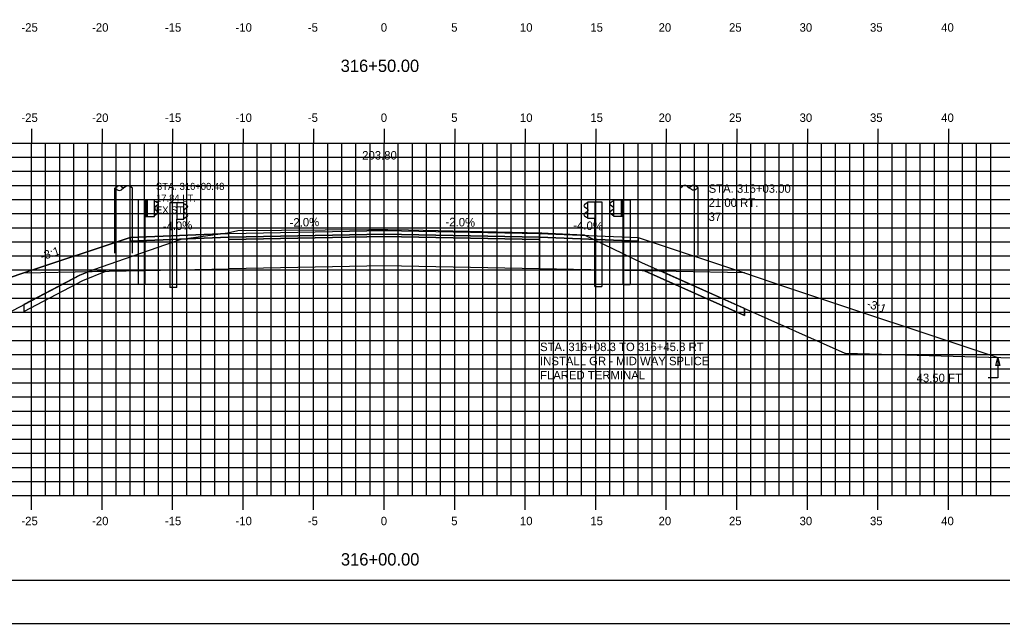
# Model space of a CAD drawing. Extents: x 1138763 to 1138933, y 608981 to 609091.
# Drawn here: x 1138820.4 to 1138890, y 608981.3 to 609024.1 of the extents above; entities that cross this region are included whole.
import ezdxf

# ---------------------------------------------------------------- set-up
doc = ezdxf.new("R2010")
doc.units = 0
for name, color, linetype in [('ANNOTATION', 7, 'Continuous'), ('BORDER', 7, 'Continuous'), ('D_Guardrail_Beam_Lt', 7, 'Continuous'), ('D_Guardrail_Beam_Rt', 7, 'Continuous'), ('D_Roadway_Centerline', 7, 'Continuous'), ('D_Roadway_Centerline_Text', 7, 'Continuous'), ('D_Roadway_Edge_Shoulder', 7, 'Continuous'), ('D_Roadway_Edge_TW', 7, 'Continuous'), ('D_Roadway_Pavement', 7, 'Continuous'), ('D_Roadway_SlopeLines', 7, 'Continuous'), ('D_Roadway_SubGrade', 7, 'Continuous'), ('D_Text_Monospaced', 7, 'Continuous'), ('D_Text_Standard', 7, 'Continuous'), ('D_Utilities_Pole_Joint_Rt', 7, 'Continuous'), ('H_V ANNOTATION', 7, 'Continuous'), ('MAJOR', 7, 'Continuous'), ('MINOR', 7, 'Continuous'), ('PLOT BOUNDARY', 7, 'Continuous'), ('S_Guardrail_Beam', 7, 'Continuous'), ('S_Roadway_Centerline', 7, 'Continuous'), ('S_Utilities_Pole_Power', 7, 'Continuous'), ('SHADING', 7, 'Continuous')]:
    doc.layers.add(name, color=color, linetype=linetype)

msp = doc.modelspace()

# ---------------------------------------------------------------- linework, layer by layer
msp.add_lwpolyline([(1138803.882, 609000.533), (1138817.659, 609005.125), (1138820.659, 609006.125), (1138828.191, 609008.636), (1138828.192, 609008.636), (1138835.192, 609008.916), (1138846.192, 609009.136), (1138857.192, 609008.916), (1138864.192, 609008.636), (1138871.724, 609006.125), (1138874.724, 609005.125), (1138889.689, 609000.137)])
at = {"layer": 'BORDER'}
msp.add_lwpolyline([(1138771.192, 608984.335), (1138931.192, 608984.335), (1138931.192, 609089.335), (1138771.192, 609089.335)], close=True, dxfattribs=at)
at = {"layer": 'D_Guardrail_Beam_Lt'}
for p, q in [((1138828.763, 609011.299), (1138828.763, 609005.299)), ((1138829.234, 609011.299), (1138828.763, 609011.299)), ((1138829.921, 609011.299), (1138829.234, 609011.299)), ((1138829.234, 609011.299), (1138829.234, 609010.132)), ((1138829.296, 609011.299), (1138829.296, 609010.132)), ((1138829.4, 609011.299), (1138829.4, 609010.132)), ((1138829.921, 609010.132), (1138829.921, 609011.299)), ((1138829.921, 609011.216), (1138829.995, 609011.201)), ((1138830.011, 609011.194), (1138830.155, 609011.094)), ((1138862.373, 609011.194), (1138862.23, 609011.094)), ((1138862.463, 609011.216), (1138862.389, 609011.201)), ((1138829.926, 609010.751), (1138829.926, 609010.681)), ((1138830.155, 609010.951), (1138829.959, 609010.815)), ((1138829.959, 609010.616), (1138830.155, 609010.48)), ((1138862.23, 609010.951), (1138862.425, 609010.815)), ((1138862.425, 609010.616), (1138862.23, 609010.48)), ((1138862.459, 609010.751), (1138862.459, 609010.681)), ((1138829.234, 609010.132), (1138829.921, 609010.132)), ((1138829.255, 609005.299), (1138829.255, 609010.132)), ((1138829.995, 609010.23), (1138829.921, 609010.216)), ((1138830.155, 609010.337), (1138830.011, 609010.237)), ((1138862.23, 609010.337), (1138862.373, 609010.237)), ((1138862.389, 609010.23), (1138862.463, 609010.216)), ((1138829.255, 609005.299), (1138828.763, 609005.299))]:
    msp.add_line(p, q, dxfattribs=at)
for centre, major_axis, start_param, end_param in [((1138829.987, 609011.16), (0.0417, 0), 0.959931, 1.376053), ((1138862.397, 609011.16), (-0.0417, 0), 4.907132, 5.323254), ((1138830.005, 609010.751), (-0.0789, 0), 5.323254, 6.283185), ((1138830.005, 609010.681), (-0.0789, 0), 6.283185, 7.243116), ((1138830.104, 609011.023), (0.0877, 0), 5.323254, 7.243116), ((1138830.104, 609010.409), (0.0877, 0), 5.323254, 7.243116), ((1138862.28, 609011.023), (-0.0877, 0), 5.323254, 7.243116), ((1138862.28, 609010.409), (-0.0877, 0), 5.323254, 7.243116), ((1138862.38, 609010.751), (0.0789, 0), 0, 0.959931), ((1138862.38, 609010.681), (0.0789, 0), 5.323254, 6.283185), ((1138829.987, 609010.271), (0.0417, 0), 4.907132, 5.323254), ((1138862.397, 609010.271), (-0.0417, 0), 0.959931, 1.376053)]:
    msp.add_ellipse(centre, major_axis=major_axis, ratio=0.995501, start_param=start_param, end_param=end_param, dxfattribs=at)
at = {"layer": 'D_Guardrail_Beam_Rt'}
for p, q in [((1138862.463, 609011.299), (1138863.15, 609011.299)), ((1138862.463, 609010.132), (1138862.463, 609011.299)), ((1138862.984, 609011.299), (1138862.984, 609010.132)), ((1138863.088, 609011.299), (1138863.088, 609010.132)), ((1138863.15, 609011.299), (1138863.621, 609011.299)), ((1138863.15, 609011.299), (1138863.15, 609010.132)), ((1138863.621, 609011.299), (1138863.621, 609005.299)), ((1138863.15, 609010.132), (1138862.463, 609010.132)), ((1138863.13, 609005.299), (1138863.13, 609010.132)), ((1138863.13, 609005.299), (1138863.621, 609005.299))]:
    msp.add_line(p, q, dxfattribs=at)
at = {"layer": 'D_Roadway_Edge_Shoulder'}
for points in [[(1138835.192, 609008.916), (1138828.192, 609008.636), (1138828.192, 609008.386), (1138835.192, 609008.666)], [(1138857.192, 609008.916), (1138864.192, 609008.636), (1138864.192, 609008.386), (1138857.192, 609008.666)]]:
    msp.add_lwpolyline(points, close=True, dxfattribs=at)
at = {"layer": 'D_Roadway_Edge_TW'}
msp.add_lwpolyline([(1138835.192, 609008.666), (1138835.192, 609008.916), (1138846.192, 609009.136), (1138857.192, 609008.916), (1138857.192, 609008.666), (1138846.192, 609008.886)], close=True, dxfattribs=at)
at = {"layer": 'D_Roadway_Pavement'}
msp.add_lwpolyline([(1138835.192, 609008.499), (1138835.192, 609008.666), (1138846.192, 609008.886), (1138857.192, 609008.666), (1138857.192, 609008.499), (1138846.192, 609008.719)], close=True, dxfattribs=at)
at = {"layer": 'D_Roadway_SlopeLines'}
for points in [[(1138820.659, 609006.125), (1138817.659, 609005.125)], [(1138820.659, 609003.884), (1138820.659, 609003.384), (1138824.82, 609005.58), (1138826.47, 609006.241)], [(1138871.724, 609003.612), (1138871.724, 609003.112), (1138864.658, 609006.266)], [(1138871.724, 609006.125), (1138874.724, 609005.125)], [(1138874.724, 609005.125), (1138889.689, 609000.137)]]:
    msp.add_lwpolyline(points, dxfattribs=at)
at = {"layer": 'D_Roadway_SubGrade'}
for points in [[(1138835.192, 609008.499), (1138835.192, 609008.666), (1138828.192, 609008.386), (1138828.192, 609008.636), (1138828.191, 609008.636), (1138820.659, 609006.125), (1138835.192, 609006.416)], [(1138835.192, 609006.416), (1138835.192, 609008.499), (1138846.192, 609008.719), (1138857.192, 609008.499), (1138857.192, 609006.416), (1138846.192, 609006.636)], [(1138857.192, 609008.499), (1138857.192, 609008.666), (1138864.192, 609008.386), (1138864.192, 609008.636), (1138864.192, 609008.636), (1138871.724, 609006.125), (1138857.192, 609006.416)]]:
    msp.add_lwpolyline(points, close=True, dxfattribs=at)
at = {"layer": 'D_Text_Standard'}
msp.add_lwpolyline([(1138889.689, 609000.137), (1138889.686, 608998.68), (1138889.006, 608998.68)], dxfattribs=at)
msp.add_lwpolyline([(1138889.689, 609000.137), (1138889.834, 608999.554), (1138889.543, 608999.555)], close=True, dxfattribs=at)
at = {"layer": 'D_Utilities_Pole_Joint_Rt'}
for p, q in [((1138867.192, 609012.169), (1138867.348, 609012.279)), ((1138867.192, 609007.411), (1138867.192, 609012.169)), ((1138867.661, 609012.279), (1138867.817, 609012.169)), ((1138867.973, 609012.279), (1138867.817, 609012.169)), ((1138867.817, 609012.169), (1138867.973, 609012.058)), ((1138868.442, 609012.169), (1138868.286, 609012.279)), ((1138868.286, 609012.058), (1138868.442, 609012.169)), ((1138868.442, 609007.411), (1138868.442, 609012.169))]:
    msp.add_line(p, q, dxfattribs=at)
for centre, start, end in [((1138867.505, 609012.058), 90, 125.26439), ((1138867.505, 609012.058), 54.73561, 90), ((1138868.13, 609012.058), 90, 125.26439), ((1138868.13, 609012.279), 234.73561, 270), ((1138868.13, 609012.058), 54.73561, 90), ((1138868.13, 609012.279), 270, 305.26439)]:
    msp.add_arc(centre, 0.271, start, end, dxfattribs=at)
at = {"layer": 'MAJOR'}
for p, q in [((1138821.192, 609016.337), (1138821.192, 609015.335)), ((1138826.192, 609016.337), (1138826.192, 609015.335)), ((1138831.192, 609016.337), (1138831.192, 609015.335)), ((1138836.192, 609016.337), (1138836.192, 609015.335)), ((1138841.192, 609016.337), (1138841.192, 609015.335)), ((1138846.192, 609016.337), (1138846.192, 609015.335)), ((1138851.192, 609016.337), (1138851.192, 609015.335)), ((1138856.192, 609016.337), (1138856.192, 609015.335)), ((1138861.192, 609016.337), (1138861.192, 609015.335)), ((1138866.192, 609016.337), (1138866.192, 609015.335)), ((1138871.192, 609016.337), (1138871.192, 609015.335)), ((1138876.192, 609016.337), (1138876.192, 609015.335)), ((1138881.192, 609016.337), (1138881.192, 609015.335)), ((1138886.192, 609016.337), (1138886.192, 609015.335)), ((1138776.192, 609015.335), (1138916.192, 609015.335)), ((1138776.192, 609015.335), (1138916.192, 609015.335)), ((1138821.192, 608990.335), (1138821.192, 609015.335)), ((1138826.192, 608990.335), (1138826.192, 609015.335)), ((1138831.192, 608990.335), (1138831.192, 609015.335)), ((1138836.192, 608990.335), (1138836.192, 609015.335)), ((1138841.192, 608990.335), (1138841.192, 609015.335)), ((1138846.192, 608990.335), (1138846.192, 609015.335)), ((1138851.192, 608990.335), (1138851.192, 609015.335)), ((1138856.192, 608990.335), (1138856.192, 609015.335)), ((1138861.192, 608990.335), (1138861.192, 609015.335)), ((1138866.192, 608990.335), (1138866.192, 609015.335)), ((1138871.192, 608990.335), (1138871.192, 609015.335)), ((1138876.192, 608990.335), (1138876.192, 609015.335)), ((1138881.192, 608990.335), (1138881.192, 609015.335)), ((1138886.192, 608990.335), (1138886.192, 609015.335)), ((1138776.192, 609010.335), (1138916.192, 609010.335)), ((1138776.192, 609005.335), (1138916.192, 609005.335)), ((1138776.192, 609000.335), (1138916.192, 609000.335)), ((1138776.192, 608995.335), (1138916.192, 608995.335)), ((1138776.192, 608990.335), (1138916.192, 608990.335)), ((1138776.192, 608990.335), (1138916.192, 608990.335)), ((1138821.192, 608989.333), (1138821.192, 608990.335)), ((1138826.192, 608989.333), (1138826.192, 608990.335)), ((1138831.192, 608989.333), (1138831.192, 608990.335)), ((1138836.192, 608989.333), (1138836.192, 608990.335)), ((1138841.192, 608989.333), (1138841.192, 608990.335)), ((1138846.192, 608989.333), (1138846.192, 608990.335)), ((1138851.192, 608989.333), (1138851.192, 608990.335)), ((1138856.192, 608989.333), (1138856.192, 608990.335)), ((1138861.192, 608989.333), (1138861.192, 608990.335)), ((1138866.192, 608989.333), (1138866.192, 608990.335)), ((1138871.192, 608989.333), (1138871.192, 608990.335)), ((1138876.192, 608989.333), (1138876.192, 608990.335)), ((1138881.192, 608989.333), (1138881.192, 608990.335)), ((1138886.192, 608989.333), (1138886.192, 608990.335))]:
    msp.add_line(p, q, dxfattribs=at)
at = {"layer": 'MINOR'}
for p, q in [((1138822.192, 608990.335), (1138822.192, 609015.335)), ((1138823.192, 608990.335), (1138823.192, 609015.335)), ((1138824.192, 608990.335), (1138824.192, 609015.335)), ((1138825.192, 608990.335), (1138825.192, 609015.335)), ((1138827.192, 608990.335), (1138827.192, 609015.335)), ((1138828.192, 608990.335), (1138828.192, 609015.335)), ((1138829.192, 608990.335), (1138829.192, 609015.335)), ((1138830.192, 608990.335), (1138830.192, 609015.335)), ((1138832.192, 608990.335), (1138832.192, 609015.335)), ((1138833.192, 608990.335), (1138833.192, 609015.335)), ((1138834.192, 608990.335), (1138834.192, 609015.335)), ((1138835.192, 608990.335), (1138835.192, 609015.335)), ((1138837.192, 608990.335), (1138837.192, 609015.335)), ((1138838.192, 608990.335), (1138838.192, 609015.335)), ((1138839.192, 608990.335), (1138839.192, 609015.335)), ((1138840.192, 608990.335), (1138840.192, 609015.335)), ((1138842.192, 608990.335), (1138842.192, 609015.335)), ((1138843.192, 608990.335), (1138843.192, 609015.335)), ((1138844.192, 608990.335), (1138844.192, 609015.335)), ((1138845.192, 608990.335), (1138845.192, 609015.335)), ((1138847.192, 608990.335), (1138847.192, 609015.335)), ((1138848.192, 608990.335), (1138848.192, 609015.335)), ((1138849.192, 608990.335), (1138849.192, 609015.335)), ((1138850.192, 608990.335), (1138850.192, 609015.335)), ((1138852.192, 608990.335), (1138852.192, 609015.335)), ((1138853.192, 608990.335), (1138853.192, 609015.335)), ((1138854.192, 608990.335), (1138854.192, 609015.335)), ((1138855.192, 608990.335), (1138855.192, 609015.335)), ((1138857.192, 608990.335), (1138857.192, 609015.335)), ((1138858.192, 608990.335), (1138858.192, 609015.335)), ((1138859.192, 608990.335), (1138859.192, 609015.335)), ((1138860.192, 608990.335), (1138860.192, 609015.335)), ((1138862.192, 608990.335), (1138862.192, 609015.335)), ((1138863.192, 608990.335), (1138863.192, 609015.335)), ((1138864.192, 608990.335), (1138864.192, 609015.335)), ((1138865.192, 608990.335), (1138865.192, 609015.335)), ((1138867.192, 608990.335), (1138867.192, 609015.335)), ((1138868.192, 608990.335), (1138868.192, 609015.335)), ((1138869.192, 608990.335), (1138869.192, 609015.335)), ((1138870.192, 608990.335), (1138870.192, 609015.335)), ((1138872.192, 608990.335), (1138872.192, 609015.335)), ((1138873.192, 608990.335), (1138873.192, 609015.335)), ((1138874.192, 608990.335), (1138874.192, 609015.335)), ((1138875.192, 608990.335), (1138875.192, 609015.335)), ((1138877.192, 608990.335), (1138877.192, 609015.335)), ((1138878.192, 608990.335), (1138878.192, 609015.335)), ((1138879.192, 608990.335), (1138879.192, 609015.335)), ((1138880.192, 608990.335), (1138880.192, 609015.335)), ((1138882.192, 608990.335), (1138882.192, 609015.335)), ((1138883.192, 608990.335), (1138883.192, 609015.335)), ((1138884.192, 608990.335), (1138884.192, 609015.335)), ((1138885.192, 608990.335), (1138885.192, 609015.335)), ((1138887.192, 608990.335), (1138887.192, 609015.335)), ((1138888.192, 608990.335), (1138888.192, 609015.335)), ((1138889.192, 608990.335), (1138889.192, 609015.335)), ((1138776.192, 609014.335), (1138916.192, 609014.335)), ((1138776.192, 609013.335), (1138916.192, 609013.335)), ((1138776.192, 609012.335), (1138916.192, 609012.335)), ((1138776.192, 609011.335), (1138916.192, 609011.335)), ((1138776.192, 609009.335), (1138916.192, 609009.335)), ((1138776.192, 609008.335), (1138916.192, 609008.335)), ((1138776.192, 609007.335), (1138916.192, 609007.335)), ((1138776.192, 609006.335), (1138916.192, 609006.335)), ((1138776.192, 609004.335), (1138916.192, 609004.335)), ((1138776.192, 609003.335), (1138916.192, 609003.335)), ((1138776.192, 609002.335), (1138916.192, 609002.335)), ((1138776.192, 609001.335), (1138916.192, 609001.335)), ((1138776.192, 608999.335), (1138916.192, 608999.335)), ((1138776.192, 608998.335), (1138916.192, 608998.335)), ((1138776.192, 608997.335), (1138916.192, 608997.335)), ((1138776.192, 608996.335), (1138916.192, 608996.335)), ((1138776.192, 608994.335), (1138916.192, 608994.335)), ((1138776.192, 608993.335), (1138916.192, 608993.335)), ((1138776.192, 608992.335), (1138916.192, 608992.335)), ((1138776.192, 608991.335), (1138916.192, 608991.335))]:
    msp.add_line(p, q, dxfattribs=at)
at = {"layer": 'PLOT BOUNDARY'}
msp.add_lwpolyline([(1138763.099, 608981.276), (1138933.099, 608981.276), (1138933.099, 609091.276), (1138763.099, 609091.276)], close=True, dxfattribs=at)
at = {"layer": 'S_Guardrail_Beam'}
for p, q in [((1138860.631, 609011.157), (1138861.12, 609011.157)), ((1138860.631, 609009.99), (1138860.631, 609011.157)), ((1138861.12, 609011.157), (1138861.612, 609011.157)), ((1138861.12, 609011.157), (1138861.12, 609009.99)), ((1138861.612, 609011.157), (1138861.612, 609005.157)), ((1138831.002, 609011.096), (1138831.002, 609005.096)), ((1138831.493, 609011.096), (1138831.002, 609011.096)), ((1138831.983, 609011.096), (1138831.493, 609011.096)), ((1138831.493, 609011.096), (1138831.493, 609009.929)), ((1138831.983, 609009.929), (1138831.983, 609011.096)), ((1138831.983, 609011.023), (1138832.065, 609011.008)), ((1138831.996, 609010.558), (1138831.996, 609010.467)), ((1138832.225, 609010.758), (1138832.03, 609010.622)), ((1138832.082, 609011.001), (1138832.225, 609010.901)), ((1138860.532, 609011.063), (1138860.389, 609010.963)), ((1138860.389, 609010.82), (1138860.584, 609010.684)), ((1138860.584, 609010.464), (1138860.389, 609010.328)), ((1138860.631, 609011.084), (1138860.549, 609011.07)), ((1138860.618, 609010.619), (1138860.618, 609010.528)), ((1138831.493, 609005.096), (1138831.493, 609009.929)), ((1138831.493, 609009.929), (1138831.983, 609009.929)), ((1138832.065, 609010.016), (1138831.983, 609010.002)), ((1138832.03, 609010.402), (1138832.225, 609010.266)), ((1138832.225, 609010.123), (1138832.082, 609010.023)), ((1138860.389, 609010.185), (1138860.532, 609010.085)), ((1138860.549, 609010.078), (1138860.631, 609010.063)), ((1138861.12, 609009.99), (1138860.631, 609009.99)), ((1138861.12, 609005.157), (1138861.12, 609009.99)), ((1138831.493, 609005.096), (1138831.002, 609005.096)), ((1138861.12, 609005.157), (1138861.612, 609005.157))]:
    msp.add_line(p, q, dxfattribs=at)
for centre, major_axis, start_param, end_param in [((1138832.075, 609010.558), (-0.0789, 0), 5.323254, 6.283185), ((1138832.075, 609010.467), (-0.0789, 0), 6.283185, 7.243116), ((1138832.058, 609010.967), (0.0417, 0), 0.959931, 1.396263), ((1138832.175, 609010.83), (0.0877, 0), 5.323254, 7.243116), ((1138860.439, 609010.891), (-0.0877, 0), 5.323254, 7.243116), ((1138860.556, 609011.029), (-0.0417, 0), 4.886922, 5.323254), ((1138860.539, 609010.619), (0.0789, 0), 0, 0.959931), ((1138860.539, 609010.528), (0.0789, 0), 5.323254, 6.283185), ((1138832.058, 609010.057), (0.0417, 0), 4.886922, 5.323254), ((1138832.175, 609010.195), (0.0877, 0), 5.323254, 7.243116), ((1138860.439, 609010.256), (-0.0877, 0), 5.323254, 7.243116), ((1138860.556, 609010.119), (-0.0417, 0), 0.959931, 1.396263)]:
    msp.add_ellipse(centre, major_axis=major_axis, ratio=0.995501, start_param=start_param, end_param=end_param, dxfattribs=at)
at = {"layer": 'S_Roadway_Centerline'}
msp.add_lwpolyline([(1138776.192, 609000.463), (1138787.534, 609000.483), (1138795.813, 609000.369), (1138801.34, 609000.501), (1138814.583, 609000.668), (1138819.911, 609003.49), (1138824.614, 609005.971), (1138825.62, 609006.374), (1138831.811, 609008.515), (1138835.077, 609008.967), (1138835.825, 609009.136), (1138845.105, 609009.195), (1138846.445, 609009.215), (1138847.926, 609009.183), (1138857.376, 609008.967), (1138857.81, 609008.955), (1138860.36, 609008.824), (1138864.437, 609006.865), (1138878.846, 609000.433), (1138878.887, 609000.44), (1138911.071, 608999.536), (1138914.413, 608999.513), (1138916.192, 608999.492)], dxfattribs=at)
at = {"layer": 'S_Utilities_Pole_Power'}
for p, q in [((1138827.099, 609012.136), (1138827.255, 609012.246)), ((1138827.099, 609007.517), (1138827.103, 609012.136)), ((1138827.255, 609012.025), (1138827.099, 609012.136)), ((1138827.568, 609012.246), (1138827.725, 609012.136)), ((1138827.725, 609012.136), (1138827.568, 609012.025)), ((1138827.881, 609012.246), (1138827.725, 609012.136)), ((1138828.349, 609012.136), (1138828.193, 609012.246)), ((1138828.349, 609007.517), (1138828.353, 609012.136))]:
    msp.add_line(p, q, dxfattribs=at)
for centre, start, end in [((1138827.412, 609012.026), 90, 125.26439), ((1138827.412, 609012.247), 234.73561, 270), ((1138827.412, 609012.026), 54.73561, 90), ((1138827.412, 609012.247), 270, 305.26439), ((1138828.037, 609012.026), 90, 125.26439), ((1138828.037, 609012.026), 54.73561, 90)]:
    msp.add_arc(centre, 0.271, start, end, dxfattribs=at)
at = {"layer": 'SHADING'}
for p, q in [((1138826.47, 609006.241), (1138825.226, 609006.216)), ((1138865.83, 609006.243), (1138864.658, 609006.266)), ((1138871.724, 609003.612), (1138865.83, 609006.243))]:
    msp.add_line(p, q, dxfattribs=at)
for points in [[(1138820.659, 609003.884), (1138820.659, 609003.384), (1138824.82, 609005.58), (1138826.47, 609006.241)], [(1138825.226, 609006.216), (1138824.614, 609005.971), (1138820.659, 609003.884)], [(1138864.658, 609006.266), (1138871.724, 609003.112), (1138871.724, 609003.612)]]:
    msp.add_lwpolyline(points, dxfattribs=at)

# ---------------------------------------------------------------- texts
at = {"layer": 'ANNOTATION'}
for s, rotation, p in [('-4.0%', 2.29061, (1138830.508, 609009.129)), ('-2.0%', 1.14576, (1138839.495, 609009.402)), ('-2.0%', 358.85424, (1138850.535, 609009.449)), ('-4.0%', 357.70939, (1138859.588, 609009.221)), ('-3:1', 18.43483, (1138821.942, 609007.007)), ('-3:1', 341.56507, (1138880.356, 609003.702))]:
    msp.add_text(s, height=0.6, rotation=rotation, dxfattribs=at).set_placement(p)
for s, p in [('STA. 316+08.3 TO 316+45.8 RT', (1138857.243, 609000.583)), ('INSTALL GR - MID WAY SPLICE', (1138857.243, 608999.581)), ('FLARED TERMINAL', (1138857.243, 608998.579))]:
    msp.add_text(s, height=0.6, dxfattribs=at).set_placement(p)
at = {"layer": 'D_Roadway_Centerline'}
for s, p in [('C', (1138846.187, 609009.136)), ('L', (1138846.192, 609009.128))]:
    msp.add_text(s, height=0.0146, dxfattribs=at).set_placement(p)
at = {"layer": 'D_Roadway_Centerline_Text'}
msp.add_text('203.80', height=0.6, dxfattribs=at).set_placement((1138844.635, 609014.168))
at = {"layer": 'D_Text_Monospaced'}
for s, height, p in [('STA. 316+00.48', 0.49998, (1138830.016, 609012.015)), ('17.84 LT.', 0.5, (1138830.016, 609011.181)), ('EXIST. ', 0.5, (1138830.016, 609010.341))]:
    msp.add_text(s, height=height, dxfattribs=at).set_placement(p)
at = {"layer": 'D_Text_Standard'}
for s, p in [('STA. 316+03.00', (1138869.192, 609011.809)), ('21.00 RT.', (1138869.192, 609010.807)), ('37 ', (1138869.192, 609009.811)), ('43.50 FT', (1138883.933, 608998.38))]:
    msp.add_text(s, height=0.6, dxfattribs=at).set_placement(p)
at = {"layer": 'H_V ANNOTATION'}
for s, height, p in [('-25', 0.6, (1138820.478, 609023.235)), ('-20', 0.6, (1138825.486, 609023.235)), ('-15', 0.6, (1138830.649, 609023.235)), ('-10', 0.6, (1138835.657, 609023.235)), ('-5', 0.6, (1138840.783, 609023.235)), ('0', 0.6, (1138845.951, 609023.235)), ('5', 0.6, (1138850.943, 609023.235)), ('10', 0.6, (1138855.817, 609023.235)), ('15', 0.6, (1138860.809, 609023.235)), ('20', 0.6, (1138865.646, 609023.235)), ('25', 0.6, (1138870.638, 609023.235)), ('30', 0.6, (1138875.641, 609023.235)), ('35', 0.6, (1138880.633, 609023.235)), ('40', 0.6, (1138885.678, 609023.235)), ('316+50.00', 0.875, (1138843.11, 609020.378)), ('-25', 0.6, (1138820.478, 609016.835)), ('-20', 0.6, (1138825.486, 609016.835)), ('-15', 0.6, (1138830.649, 609016.835)), ('-10', 0.6, (1138835.657, 609016.835)), ('-5', 0.6, (1138840.783, 609016.835)), ('0', 0.6, (1138845.951, 609016.835)), ('5', 0.6, (1138850.943, 609016.835)), ('10', 0.6, (1138855.817, 609016.835)), ('15', 0.6, (1138860.809, 609016.835)), ('20', 0.6, (1138865.646, 609016.835)), ('25', 0.6, (1138870.638, 609016.835)), ('30', 0.6, (1138875.641, 609016.835)), ('35', 0.6, (1138880.633, 609016.835)), ('40', 0.6, (1138885.678, 609016.835)), ('-25', 0.6, (1138820.478, 608988.235)), ('-20', 0.6, (1138825.486, 608988.235)), ('-15', 0.6, (1138830.649, 608988.235)), ('-10', 0.6, (1138835.657, 608988.235)), ('-5', 0.6, (1138840.783, 608988.235)), ('0', 0.6, (1138845.951, 608988.235)), ('5', 0.6, (1138850.943, 608988.235)), ('10', 0.6, (1138855.817, 608988.235)), ('15', 0.6, (1138860.809, 608988.235)), ('20', 0.6, (1138865.646, 608988.235)), ('25', 0.6, (1138870.638, 608988.235)), ('30', 0.6, (1138875.641, 608988.235)), ('35', 0.6, (1138880.633, 608988.235)), ('40', 0.6, (1138885.678, 608988.235)), ('316+00.00', 0.875, (1138843.126, 608985.378))]:
    msp.add_text(s, height=height, dxfattribs=at).set_placement(p)
at = {"layer": 'S_Roadway_Centerline'}
for s, p in [('C', (1138846.44, 609009.215)), ('L', (1138846.445, 609009.207))]:
    msp.add_text(s, height=0.0146, dxfattribs=at).set_placement(p)

doc.saveas('drawing.dxf')
